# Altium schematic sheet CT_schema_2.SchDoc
size 461 x 327 mm
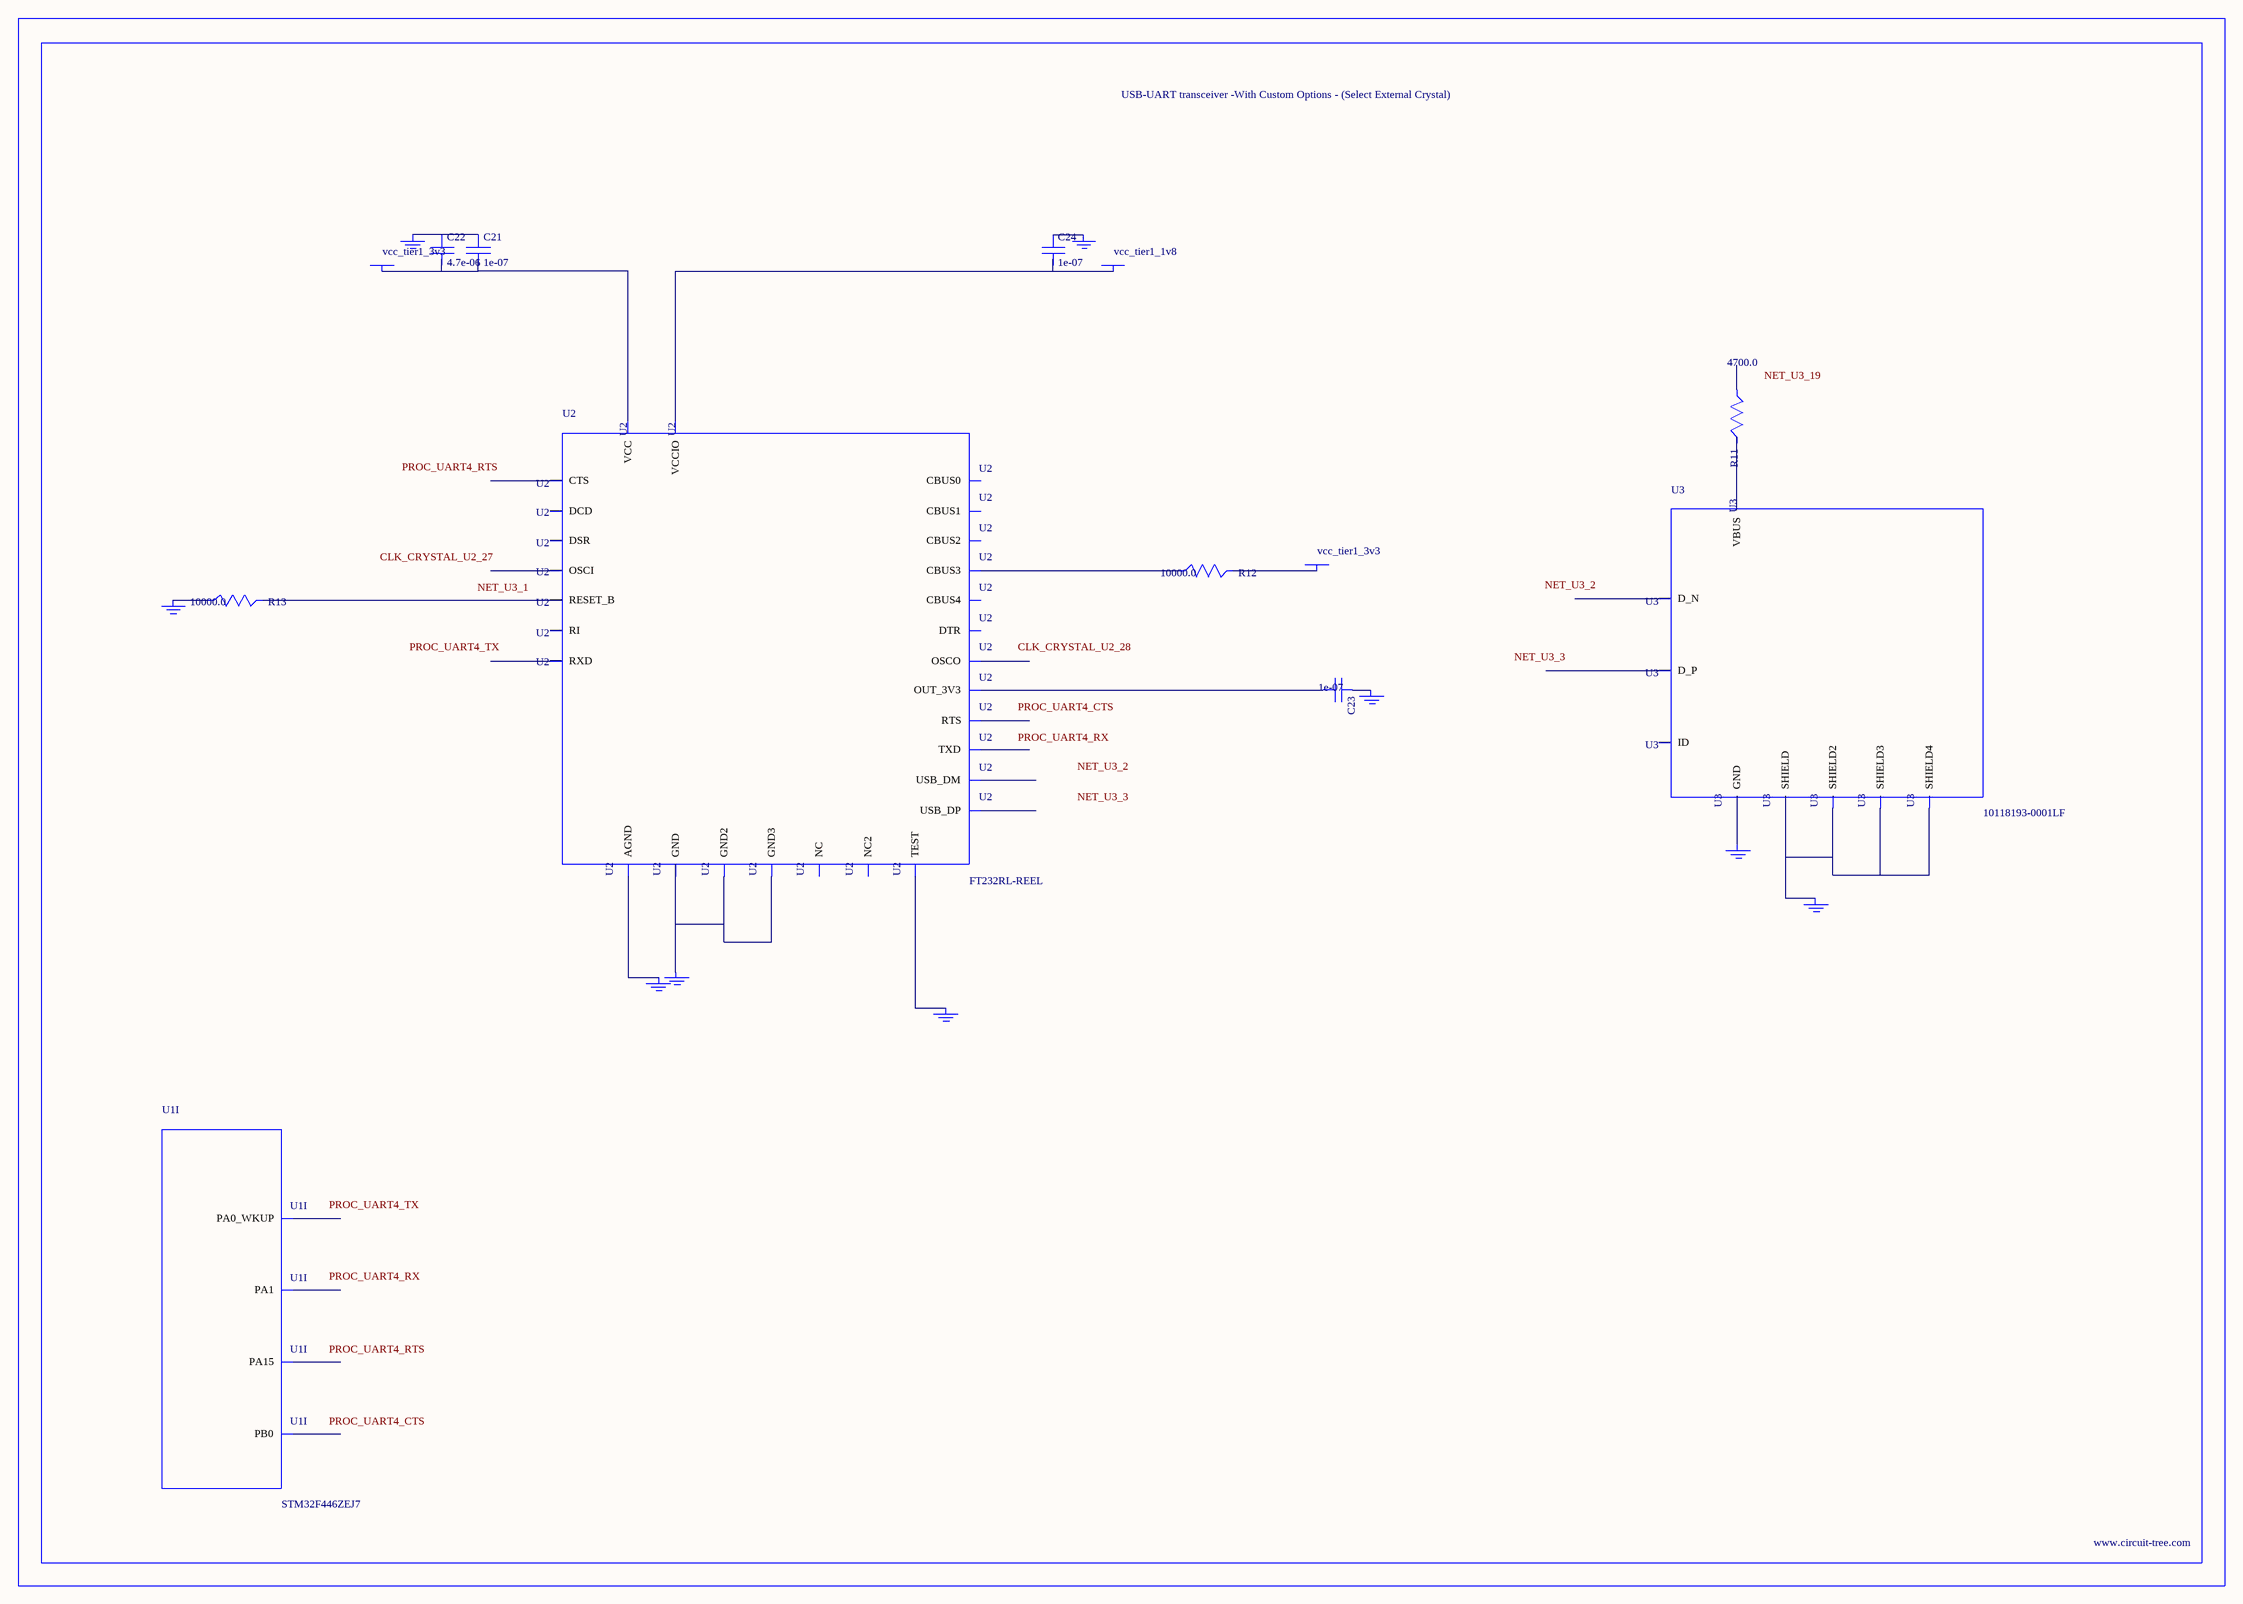
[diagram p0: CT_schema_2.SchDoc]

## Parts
BORDER1  (no value)
C21  1e-07  [C0402]
C22  4.7e-06  [C0805]
C23  1e-07  [C0402]
C24  1e-07  [C0402]
GND_INSTANCE_1_0  (no value)
GND_INSTANCE_1_1  (no value)
GND_INSTANCE_1_2  (no value)
GND_INSTANCE_1_3  (no value)
GND_INSTANCE_1_4  (no value)
GND_INSTANCE_1_5  (no value)
GND_INSTANCE_1_6  (no value)
GND_INSTANCE_1_7  (no value)
GND_INSTANCE_1_8  (no value)
POWER_INSTANCE_1_0  vcc_tier1_1v8
POWER_INSTANCE_1_1  vcc_tier1_3v3
POWER_INSTANCE_1_2  vcc_tier1_3v3
R11  4700.0  [R0603]
R12  10000.0  [R0603]
R13  10000.0  [R0603]
U1  STM32F446ZEJ7  [UFBGA144]  (part I of 12)
U2  FT232RL-REEL  [SSOP-28]
U3  10118193-0001LF  [FCI_10118193-0001LF]

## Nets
NetC21_1: C21.1 C22.1 GND_INSTANCE_1_3.0(GND)
NetC21_2: C21.2 C22.2 POWER_INSTANCE_1_2.0(PWR) U2.20(VCC)
NetC23_1: C23.1 GND_INSTANCE_1_1.0(GND)
NetC23_2: C23.2 U2.17(OUT_3V3)
NetC24_1: C24.1 GND_INSTANCE_1_0.0(GND)
NetC24_2: C24.2 POWER_INSTANCE_1_0.0(PWR) U2.4(VCCIO)
NetGND_INSTANCE_1_2_0: GND_INSTANCE_1_2.0(GND) R13.1
NetGND_INSTANCE_1_4_0: GND_INSTANCE_1_4.0(GND) U2.25(AGND)
NetGND_INSTANCE_1_5_0: GND_INSTANCE_1_5.0(GND) U2.26(TEST)
NetGND_INSTANCE_1_6_0: GND_INSTANCE_1_6.0(GND) U2.7(GND) U2.18(GND2) U2.21(GND3)
NetGND_INSTANCE_1_7_0: GND_INSTANCE_1_7.0(GND) U3.6(SHIELD) U3.7(SHIELD2) U3.8(SHIELD3) U3.9(SHIELD4)
NetGND_INSTANCE_1_8_0: GND_INSTANCE_1_8.0(GND) U3.5(GND)
NetPOWER_INSTANCE_1_1_0: POWER_INSTANCE_1_1.0(PWR) R12.2
NetR11_2: R11.2 U3.1(VBUS)
NetR12_1: R12.1 U2.14(CBUS3)
NetR13_2: R13.2 U2.19(RESET_B)

Not connected (* = marked no-connect by the designer): R11 1; U1 A10(PA15) J2(PA0_WKUP) K2(PA1) L4(PB0); U2 1(TXD) 2(DTR) 3(RTS) 5(RXD) 6(RI) 8(NC) 9(DSR) 10(DCD) 11(CTS) 12(CBUS4) 13(CBUS2) 15(USB_DP) 16(USB_DM) 22(CBUS1) 23(CBUS0) 24(NC2) 27(OSCI) 28(OSCO); U3 2(D_N) 3(D_P) 4(ID)

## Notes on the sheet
- Labels drawn without touching a wire or pin: CLK_CRYSTAL_U2_27, CLK_CRYSTAL_U2_28, NET_U3_1, NET_U3_2, NET_U3_3, NET_U3_19, PROC_UART4_CTS, PROC_UART4_RTS, PROC_UART4_RX, PROC_UART4_TX

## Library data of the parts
BORDER1 = BORDER_PAGE1
C21 C23 C24 = C0402C104K3RACTU
C22 = C0805C475K4RACTU
GND_INSTANCE_1_0-GND_INSTANCE_1_8 = GND
POWER_INSTANCE_1_0-POWER_INSTANCE_1_2 = PWR
R11 = RC0603JR-074K7L
R12 R13 = RC0603JR-0710KL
